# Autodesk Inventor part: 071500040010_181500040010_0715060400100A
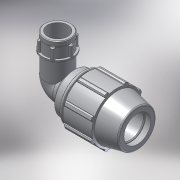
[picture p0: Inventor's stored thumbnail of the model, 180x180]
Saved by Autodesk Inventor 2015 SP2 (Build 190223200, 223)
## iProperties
Created: 2017-02
Part Number: 071500040010_181500040010_0715060400100A
Material: PVC-Piping
Description: PLASSON 90° ELBOW FEMALE ADAPTOR 40-1"
Document SubType Name: Modeling
Designer: KIM
Mass: 92.6774 g
Surface Area: 199.44 cm^2
Volume: 66.1981 cm^3
Density: 1.4 g/cm^3
Appearance: Smooth - White
Author: KIM
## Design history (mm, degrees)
derived "07150.ipt"
feature "Solid1::07150.ipt"
tag "TaggingFeature1"
body "Solid1"
other parameters: "d4" = 9.91667, "d5" = 29.75, "d7" = 82, "d9" = 17, "d11" = 3.96667, "d13" = 120 deg, "d14" = 56, "d15" = 12 deg, "d16" = 71.34, "d18" = 2, "d19" = 35 deg, "d20" = 17.5 deg, "d21" = 76.26, "d23" = 0, "d25" = 360 deg, "d27" = 1.64, "d33" = 0.8, "d42" = 44.03, "d43" = 2.46, "d46" = 1.2, "d51" = 119, "d68" = 3.96667, "d72" = 52, "d73" = 39.3783, "d74" = 21, "d75" = 45.28505, "d76" = 30.291, "d77" = 23.1, "d79" = 12.1164, "d80" = 0.90873, "d83" = 0, "d84" = 0, "d91" = 61.5, "d93" = 84, "d94" = 30.291, "d95" = 21.2037, "d96" = 9.91667, "d97" = 50 deg, "d98" = 27.2619, "d99" = 0.5, "d100" = 0.5, "d101" = 7, "d102" = 39.3783, "d103" = 17.85, "d104" = 0, "d108" = 360 deg, "d110" = 1.18135, "E_" = 82, "A_" = 119, "l_" = 84, "l_2" = 21, "A_1" = 52, "Rp_" = 30.291, "d105" = 5.90674
